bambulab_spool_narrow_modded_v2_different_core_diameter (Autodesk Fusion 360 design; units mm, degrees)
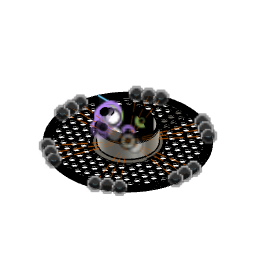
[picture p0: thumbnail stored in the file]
parameter "hole_distance_from_top" = 12.75
parameter "hole_distance_from_sides" = 32
parameter "lattice_thickness" = 3.75
parameter "lattice_diameter" = 10.25
parameter "hole_diameter" = 3.5 comment "The hole diameter around the rim"
parameter "center_core_outer_diameter" = 74 comment "The outer diameter the core should have, must be between 69 and 80 (inclusive)"
base_mesh_feature "Base Mesh Feature"
convert_mesh "Convert Mesh"
sketch "Sketch1" plane through (0, 0, -13.45) normal (0, 0, 1) x axis (-1, 0, 0)
  line L1 (91.1991, -17.1626) -> (97.9893, -17.84)
  line L2 (90.8249, -19.0441) -> (91.1991, -17.1626)
  line L3 (97.9893, -17.84) -> (90.8249, -19.0441)
  line L4 (94.8205, 15.0016) -> (94.8184, -14.9969)
  line L5 (34.4185, 89.6178) -> (60.3969, 74.6167)
  line L6 (-60.402, 74.6162) -> (-34.4215, 89.6136)
  line L7 (-94.8205, -15.0016) -> (-94.8184, 14.9969)
  line L8 (-34.4185, -89.6178) -> (-60.3969, -74.6167)
  line L9 (60.402, -74.6162) -> (34.4215, -89.6136)
  line L10 (0, 0) -> (47.4118, -82.1149)
  line L11 (-47.4077, -82.1173) -> (0, 0)
  line L12 (-94.8195, -0.0023) -> (0, 0)
  line L13 (-47.4118, 82.1149) -> (0, 0)
  line L14 (47.4077, 82.1173) -> (0, 0)
  line L15 (94.8195, 0.0023) -> (0, 0)
  line L16 (0, 0) -> (60.3969, 74.6167)
  line L17 (34.4185, 89.6178) -> (0, 0)
  line L18 (-34.4215, 89.6136) -> (0, 0)
  line L19 (-60.402, 74.6162) -> (0, 0)
  line L20 (-94.8184, 14.9969) -> (0, 0)
  line L21 (-94.8205, -15.0016) -> (0, 0)
  line L22 (-34.4185, -89.6178) -> (0, 0)
  line L23 (-60.3969, -74.6167) -> (0, 0)
  line L24 (34.4215, -89.6136) -> (0, 0)
  line L25 (60.402, -74.6162) -> (0, 0)
  line L26 (94.8184, -14.9969) -> (0, 0)
  line L27 (94.8205, 15.0016) -> (0, 0)
  circle C1 centre (94.8184, -14.9969) radius 2
  circle C2 centre (94.8205, 15.0016) radius 2
  circle C3 centre (60.3969, 74.6167) radius 2
  circle C4 centre (-34.4215, 89.6136) radius 2
  circle C5 centre (-94.8184, 14.9969) radius 2
  circle C6 centre (-60.3969, -74.6167) radius 2
  circle C7 centre (34.4215, -89.6136) radius 2
  circle C8 centre (34.4185, 89.6178) radius 2
  circle C9 centre (-60.402, 74.6162) radius 2
  circle C10 centre (-94.8205, -15.0016) radius 2
  circle C11 centre (-34.4185, -89.6178) radius 2
  circle C12 centre (60.402, -74.6162) radius 2
  point P1 (0, 0)
  point P7 (0, 0)
  point P5 (94.8184, -14.9969)
  point P18 (94.8184, -14.9969)
  point P6 (94.8205, 15.0016)
  point P19 (94.8205, 15.0016)
  point P8 (60.3969, 74.6167)
  point P20 (60.3969, 74.6167)
  point P13 (34.4185, 89.6178)
  point P21 (34.4185, 89.6178)
  point P9 (-34.4215, 89.6136)
  point P22 (-34.4215, 89.6136)
  point P14 (-60.402, 74.6162)
  point P23 (-60.402, 74.6162)
  point P10 (-94.8184, 14.9969)
  point P24 (-94.8184, 14.9969)
  point P15 (-94.8205, -15.0016)
  point P25 (-94.8205, -15.0016)
  point P11 (-60.3969, -74.6167)
  point P26 (-60.3969, -74.6167)
  point P16 (-34.4185, -89.6178)
  point P27 (-34.4185, -89.6178)
  point P12 (34.4215, -89.6136)
  point P28 (34.4215, -89.6136)
  point P17 (60.402, -74.6162)
  point P29 (60.402, -74.6162)
  point P30 (47.4118, -82.1149)
  point P31 (94.8195, 0.0023)
  point P32 (-47.4077, -82.1173)
  point P33 (-94.8195, -0.0023)
  point P34 (-47.4118, 82.1149)
  point P35 (47.4077, 82.1173)
  point P36 (47.4118, -82.1149)
  point P37 (0, 0)
  point P38 (-47.4077, -82.1173)
  point P39 (0, 0)
  point P40 (-94.8195, -0.0023)
  point P41 (0, 0)
  point P42 (-47.4118, 82.1149)
  point P43 (0, 0)
  point P44 (47.4077, 82.1173)
  point P45 (0, 0)
  point P46 (94.8195, 0.0023)
  point P47 (0, 0)
  point P48 (34.4185, 89.6178)
  point P49 (0, 0)
  point P50 (-34.4215, 89.6136)
  point P51 (0, 0)
  point P52 (-94.8184, 14.9969)
  point P53 (0, 0)
  point P54 (-94.8205, -15.0016)
  point P55 (-34.4185, -89.6178)
  point P56 (-60.3969, -74.6167)
  point P57 (0, 0)
  point P58 (60.402, -74.6162)
  point P59 (0, 0)
  point P60 (94.8184, -14.9969)
  point P61 (0, 0)
  point P62 (94.8205, 15.0016)
  coincident P1 P7
  coincident P5 P18
  coincident P6 P19
  coincident P8 P20
  coincident P13 P21
  coincident P9 P22
  coincident P14 P23
  coincident P10 P24
  coincident P15 P25
  coincident P11 P26
  coincident P16 P27
  coincident P12 P28
  coincident P17 P29
  midpoint L9 P30
  midpoint L4 P31
  midpoint L8 P32
  midpoint L7 P33
  midpoint L6 P34
  midpoint L5 P35
  coincident P30 P36
  coincident P1 P37
  coincident P32 P38
  coincident P1 P39
  coincident P33 P40
  coincident P7 P41
  coincident P34 P42
  coincident P7 P43
  coincident P35 P44
  coincident P1 P45
  coincident P31 P46
  coincident P7 P47
  coincident P13 P48
  coincident P7 P49
  coincident P9 P50
  coincident P7 P51
  coincident P10 P52
  coincident P7 P53
  coincident P15 P54
  coincident P16 P55
  coincident P11 P56
  coincident P1 P57
  coincident P17 P58
  coincident P1 P59
  coincident P5 P60
  coincident P7 P61
  coincident P6 P62
  dimension "d1" diameter C2 = 4
  dimension "d2" diameter C1 = 4
  dimension "d4" C-Pattern1-Angle = 360
  dimension "d6" C-Pattern2-Angle = 360
extrude "Extrude1" cut sketch "Sketch1" profile of C3 C4 C6 C7 C8 C9 C11 C12 against normal blind 11
sketch "Sketch2" plane through (0, 0, 0) normal (1, 0, 0) x axis (0, 1, 0)
  line L1 (0, -25) -> (0, 24)
  line L2 (-63, 0) -> (50, 0)
  circle C1 centre (-32, -12.75) radius 1.1
  circle C2 centre (32, -12.75) radius 1.1
  point P2 (-32, -12.75)
  point P3 (32, -12.75)
  vertical L1
  horizontal L2
  dimension "d9" diameter C2 = 2.2
  dimension "d10" diameter C1 = 2.2
  dimension "d11" distance P2 L1 = 32 (= "hole_distance_from_sides")
  dimension "d12" distance P3 L1 = 32 (= "hole_distance_from_sides")
  dimension "d13" distance P3 L2 = 12.75 (= "hole_distance_from_top")
  dimension "d16" distance P2 L2 = 12.75 (= "hole_distance_from_top")
work_plane "WorkPlane1" AlongDistance -61
work_plane "WorkPlane2" AlongDistance -64
work_plane "WorkPlane3" AlongDistance 64
work_plane "WorkPlane4" AlongDistance 65
sketch "Sketch3" plane through (64, 0, 0) normal (1, 0, 0) x axis (0, 1, 0)
  circle C1 centre (-32, -12.75) radius 1.1
  circle C2 centre (32, -12.75) radius 1.1
extrude "Extrude2" cut sketch "Sketch3" against normal blind 57
sketch "Sketch4" plane through (-61, 0, 0) normal (1, 0, 0) x axis (0, 1, 0)
  circle C1 centre (32, -12.75) radius 1.1
  circle C2 centre (-32, -12.75) radius 1.1
extrude "Extrude3" cut sketch "Sketch4" along normal blind 56
sketch "Sketch5" plane through (0, 65, 0) normal (0, 1, 0) x axis (1, 0, 0)
  line L1 (0, 26) -> (0, -23)
  line L2 (-49.4611, 0) -> (56, 0)
  circle C1 centre (32, 12.75) radius 1.1
  circle C2 centre (-32, 12.75) radius 1.1
  point P7 (-32, 12.75)
  point P6 (32, 12.75)
  vertical L1
  horizontal L2
  dimension "d25" diameter C1 = 2.2
  dimension "d26" diameter C2 = 2.2
  dimension "d27" distance L2 P7 = 12.75 (= "hole_distance_from_top")
  dimension "d28" distance L2 P6 = 12.75 (= "hole_distance_from_top")
  dimension "d29" distance L1 P6 = 32 (= "hole_distance_from_sides")
  dimension "d30" distance L1 P7 = 32 (= "hole_distance_from_sides")
extrude "Extrude4" cut sketch "Sketch5" profile of C1 C2 against normal blind 60
sketch "Sketch6" plane through (0, -64, 0) normal (0, 1, 0) x axis (1, 0, 0)
  circle C1 centre (32, 12.75) radius 1.1
  circle C2 centre (-32, 12.75) radius 1.1
extrude "Extrude5" cut sketch "Sketch6" along normal blind 60
sketch "Label" plane through (0, 0, -17.05) normal (0, 0, -1) x axis (1, 0, 0)
  line L1 (-1.2532, -46.0788) -> (-0.6281, -46.0197)
  line L2 (-1.8735, -46.1771) -> (-1.2532, -46.0788)
  line L3 (-2.4873, -46.3143) -> (-1.8735, -46.1771)
  line L4 (-3.0901, -46.4894) -> (-2.4873, -46.3143)
  line L5 (-3.6808, -46.7021) -> (-3.0901, -46.4894)
  line L6 (-0.6281, -46.0197) -> (0, -46.0001)
  line L7 (0.6281, -46.0197) -> (0, -46.0001)
  line L8 (1.2532, -46.0788) -> (0.6281, -46.0197)
  line L9 (1.8735, -46.1771) -> (1.2532, -46.0788)
  line L10 (2.4872, -46.3143) -> (1.8735, -46.1771)
  line L11 (3.0901, -46.4894) -> (2.4872, -46.3143)
  line L12 (3.6808, -46.7021) -> (3.0901, -46.4894)
  line L13 (4.2582, -46.9519) -> (3.6808, -46.7021)
  line L14 (4.8175, -47.2369) -> (4.2582, -46.9519)
  line L15 (5.3579, -47.5565) -> (4.8175, -47.2369)
  line L16 (5.878, -47.91) -> (5.3579, -47.5565)
  line L17 (6.3742, -48.2949) -> (5.878, -47.91)
  line L18 (6.8453, -48.7102) -> (6.3742, -48.2949)
  line L19 (7.2897, -49.1546) -> (6.8453, -48.7102)
  line L20 (7.7051, -49.6258) -> (7.2897, -49.1546)
  line L21 (8.0901, -50.1221) -> (7.7051, -49.6258)
  line L22 (8.4431, -50.6416) -> (8.0901, -50.1221)
  line L23 (8.7631, -51.1825) -> (8.4431, -50.6416)
  line L24 (9.0483, -51.7422) -> (8.7631, -51.1825)
  line L25 (9.2976, -52.3185) -> (9.0483, -51.7422)
  line L26 (9.5106, -52.91) -> (9.2976, -52.3185)
  line L27 (9.6858, -53.5131) -> (9.5106, -52.91)
  line L28 (9.8228, -54.1259) -> (9.6858, -53.5131)
  line L29 (9.9212, -54.7468) -> (9.8228, -54.1259)
  line L30 (9.9802, -55.3716) -> (9.9212, -54.7468)
  line L31 (10, -56) -> (9.9802, -55.3716)
  line L32 (10, -82) -> (10, -56)
  line L33 (-9.2976, -52.3185) -> (-9.0483, -51.7422)
  line L34 (-9.0483, -51.7422) -> (-8.7631, -51.1825)
  line L35 (-8.7631, -51.1825) -> (-8.4431, -50.6416)
  line L36 (-8.4431, -50.6416) -> (-8.0901, -50.1221)
  line L37 (-8.0901, -50.1221) -> (-7.7051, -49.6258)
  line L38 (-7.7051, -49.6258) -> (-7.2897, -49.1546)
  line L39 (-7.2897, -49.1546) -> (-6.8453, -48.7102)
  line L40 (-6.8453, -48.7102) -> (-6.3742, -48.2949)
  line L41 (-6.3742, -48.2949) -> (-5.878, -47.91)
  line L42 (-5.878, -47.91) -> (-5.3579, -47.5565)
  line L43 (-5.3579, -47.5565) -> (-4.8175, -47.2369)
  line L44 (-4.8175, -47.2369) -> (-4.2582, -46.9519)
  line L45 (-4.2582, -46.9519) -> (-3.6808, -46.7021)
  line L46 (-9.5106, -52.91) -> (-9.2976, -52.3185)
  line L47 (-9.6858, -53.5131) -> (-9.5106, -52.91)
  line L48 (-9.8228, -54.1259) -> (-9.6858, -53.5131)
  line L49 (-9.9212, -54.7468) -> (-9.8228, -54.1259)
  line L50 (-9.9802, -55.3716) -> (-9.9212, -54.7468)
  line L51 (-10, -56) -> (-9.9802, -55.3716)
  line L52 (-10, -82) -> (-10, -56)
  line L53 (9.9802, -82.6284) -> (10, -82)
  line L54 (9.9212, -83.2532) -> (9.9802, -82.6284)
  line L55 (9.8228, -83.8741) -> (9.9212, -83.2532)
  line L56 (9.6858, -84.4869) -> (9.8228, -83.8741)
  line L57 (9.5106, -85.09) -> (9.6858, -84.4869)
  line L58 (9.2976, -85.6815) -> (9.5106, -85.09)
  line L59 (9.0483, -86.2578) -> (9.2976, -85.6815)
  line L60 (8.7631, -86.8175) -> (9.0483, -86.2578)
  line L61 (8.4431, -87.3584) -> (8.7631, -86.8175)
  line L62 (8.0901, -87.8779) -> (8.4431, -87.3584)
  line L63 (7.7051, -88.3742) -> (8.0901, -87.8779)
  line L64 (7.2897, -88.8454) -> (7.7051, -88.3742)
  line L65 (6.8453, -89.2898) -> (7.2897, -88.8454)
  line L66 (6.3742, -89.7051) -> (6.8453, -89.2898)
  line L67 (5.878, -90.09) -> (6.3742, -89.7051)
  line L68 (5.3579, -90.4435) -> (5.878, -90.09)
  line L69 (4.8175, -90.7631) -> (5.3579, -90.4435)
  line L70 (4.2582, -91.0481) -> (4.8175, -90.7631)
  line L71 (3.6808, -91.2979) -> (4.2582, -91.0481)
  line L72 (3.0901, -91.5106) -> (3.6808, -91.2979)
  line L73 (2.4872, -91.6857) -> (3.0901, -91.5106)
  line L74 (1.8735, -91.8229) -> (2.4872, -91.6857)
  line L75 (1.2532, -91.9212) -> (1.8735, -91.8229)
  line L76 (0.6281, -91.9803) -> (1.2532, -91.9212)
  line L77 (0, -92) -> (0.6281, -91.9803)
  line L78 (0, -92) -> (-0.6281, -91.9803)
  line L79 (-0.6281, -91.9803) -> (-1.2532, -91.9212)
  line L80 (-1.2532, -91.9212) -> (-1.8735, -91.8229)
  line L81 (-1.8735, -91.8229) -> (-2.4873, -91.6857)
  line L82 (-2.4873, -91.6857) -> (-3.0901, -91.5106)
  line L83 (-3.0901, -91.5106) -> (-3.6808, -91.2979)
  line L84 (-3.6808, -91.2979) -> (-4.2582, -91.0481)
  line L85 (-4.2582, -91.0481) -> (-4.8175, -90.7631)
  line L86 (-4.8175, -90.7631) -> (-5.3579, -90.4435)
  line L87 (-5.3579, -90.4435) -> (-5.878, -90.09)
  line L88 (-5.878, -90.09) -> (-6.3742, -89.7051)
  line L89 (-6.3742, -89.7051) -> (-6.8453, -89.2898)
  line L90 (-6.8453, -89.2898) -> (-7.2897, -88.8454)
  line L91 (-7.2897, -88.8454) -> (-7.7051, -88.3742)
  line L92 (-7.7051, -88.3742) -> (-8.0901, -87.8779)
  line L93 (-8.0901, -87.8779) -> (-8.4431, -87.3584)
  line L94 (-8.4431, -87.3584) -> (-8.7631, -86.8175)
  line L95 (-8.7631, -86.8175) -> (-9.0483, -86.2578)
  line L96 (-9.0483, -86.2578) -> (-9.2976, -85.6815)
  line L97 (-9.2976, -85.6815) -> (-9.5106, -85.09)
  line L98 (-9.5106, -85.09) -> (-9.6858, -84.4869)
  line L99 (-9.6858, -84.4869) -> (-9.8228, -83.8741)
  line L100 (-9.8228, -83.8741) -> (-9.9212, -83.2532)
  line L101 (-9.9212, -83.2532) -> (-9.9802, -82.6284)
  line L102 (-9.9802, -82.6284) -> (-10, -82)
  line L103 (-10.3182, -83.3033) -> (-10.3796, -82.6536)
  line L104 (-10.2159, -83.9491) -> (-10.3182, -83.3033)
  line L105 (-10.0734, -84.5864) -> (-10.2159, -83.9491)
  line L106 (-9.8912, -85.2136) -> (-10.0734, -84.5864)
  line L107 (-9.6697, -85.8289) -> (-9.8912, -85.2136)
  line L108 (-9.4104, -86.4282) -> (-9.6697, -85.8289)
  line L109 (-9.1138, -87.0103) -> (-9.4104, -86.4282)
  line L110 (-8.781, -87.5728) -> (-9.1138, -87.0103)
  line L111 (-8.4139, -88.1131) -> (-8.781, -87.5728)
  line L112 (-8.0135, -88.6293) -> (-8.4139, -88.1131)
  line L113 (-7.5814, -89.1194) -> (-8.0135, -88.6293)
  line L114 (-7.1193, -89.5816) -> (-7.5814, -89.1194)
  line L115 (-6.6293, -90.0135) -> (-7.1193, -89.5816)
  line L116 (-6.1133, -90.4137) -> (-6.6293, -90.0135)
  line L117 (-5.5723, -90.7814) -> (-6.1133, -90.4137)
  line L118 (-5.0103, -91.1138) -> (-5.5723, -90.7814)
  line L119 (-4.4285, -91.4102) -> (-5.0103, -91.1138)
  line L120 (-3.8281, -91.67) -> (-4.4285, -91.4102)
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  dimension "d59" = 0.4
sketch "Sketch7" plane through (0, 0, -14.55) normal (0, 0, 1) x axis (-1, 0, 0)
  line L1 (-2.5625, -4.4384) -> (-5.125, 0)
  line L2 (-5.125, 0) -> (-2.5625, 4.4384)
  line L3 (8.3726, -10.7518) -> (5.8101, -6.3134)
  line L4 (16.0601, -6.3134) -> (13.4976, -10.7518)
  line L5 (13.4976, -10.7518) -> (8.3726, -10.7518)
  line L6 (2.5625, -8.1884) -> (5.125, -12.6268)
  line L7 (5.125, -12.6268) -> (2.5625, -17.0651)
  line L8 (16.0601, -17.0651) -> (16.0601, 10.7518)
  line L9 (2.5625, -17.0651) -> (-2.5625, -17.0651)
  line L10 (5.125, 0) -> (2.5625, -4.4384)
  line L11 (-2.5625, 4.4384) -> (2.5625, 4.4384)
  line L12 (-5.125, -17.0651) -> (16.0601, -17.0651)
  line L13 (-5.125, 10.7518) -> (16.0601, 10.7518)
  line L14 (-37, 0) -> (37, 0)
  line L15 (2.5625, -4.4384) -> (-2.5625, -4.4384)
  line L16 (-2.5625, -17.0651) -> (-5.125, -12.6268)
  line L17 (2.5625, 4.4384) -> (5.125, 0)
  line L18 (13.4976, 10.7518) -> (16.0601, 6.3134)
  line L19 (5.8101, 6.3134) -> (8.3726, 10.7518)
  line L20 (16.0601, 6.3134) -> (13.4976, 1.875)
  line L21 (13.4976, 1.875) -> (8.3726, 1.875)
  line L22 (-2.5625, -8.1884) -> (2.5625, -8.1884)
  line L23 (8.3726, 10.7518) -> (13.4976, 10.7518)
  line L24 (8.3726, -1.875) -> (13.4976, -1.875)
  line L25 (8.3726, 1.875) -> (5.8101, 6.3134)
  line L26 (5.8101, -6.3134) -> (8.3726, -1.875)
  line L27 (13.4976, -1.875) -> (16.0601, -6.3134)
  line L28 (-5.125, -17.0651) -> (-5.125, 10.7518)
  line L29 (0, -45.5) -> (0, 45.5)
  line L30 (-5.125, -12.6268) -> (-2.5625, -8.1884)
  line L31 (-100.8005, -108.8944) -> (-103.363, -113.3327)
  line L32 (-103.363, -113.3327) -> (-108.488, -113.3327)
  line L33 (-108.488, -113.3327) -> (-111.0505, -108.8944)
  line L34 (-111.0505, -108.8944) -> (-108.488, -104.456)
  line L35 (-108.488, -104.456) -> (-103.363, -104.456)
  line L36 (-103.363, -104.456) -> (-100.8005, -108.8944)
  line L37 (-97.5529, -107.0194) -> (-100.1154, -102.581)
  line L38 (-92.4279, -107.0194) -> (-97.5529, -107.0194)
  line L39 (-89.8654, -102.581) -> (-92.4279, -107.0194)
  line L40 (-92.4279, -98.1426) -> (-89.8654, -102.581)
  line L41 (-97.5529, -98.1426) -> (-92.4279, -98.1426)
  line L42 (-100.1154, -102.581) -> (-97.5529, -98.1426)
  line L43 (-100.8005, -96.2676) -> (-103.363, -100.706)
  line L44 (-103.363, -100.706) -> (-108.488, -100.706)
  line L45 (-108.488, -100.706) -> (-111.0505, -96.2676)
  line L46 (-111.0505, -96.2676) -> (-108.488, -91.8292)
  line L47 (-108.488, -91.8292) -> (-103.363, -91.8292)
  line L48 (-103.363, -91.8292) -> (-100.8005, -96.2676)
  line L49 (-97.5529, -94.3926) -> (-100.1154, -89.9542)
  line L50 (-92.4279, -94.3926) -> (-97.5529, -94.3926)
  line L51 (-89.8654, -89.9542) -> (-92.4279, -94.3926)
  line L52 (-92.4279, -85.5158) -> (-89.8654, -89.9542)
  line L53 (-100.1154, -89.9542) -> (-97.5529, -85.5158)
  line L54 (-97.5529, -85.5158) -> (-92.4279, -85.5158)
  line L55 (-79.6154, -108.8944) -> (-82.1779, -113.3327)
  line L56 (-82.1779, -113.3327) -> (-87.3029, -113.3327)
  line L57 (-87.3029, -113.3327) -> (-89.8654, -108.8944)
  line L58 (-89.8654, -108.8944) -> (-87.3029, -104.456)
  line L59 (-87.3029, -104.456) -> (-82.1779, -104.456)
  line L60 (-82.1779, -104.456) -> (-79.6154, -108.8944)
  line L61 (-76.3678, -107.0194) -> (-78.9303, -102.581)
  line L62 (-71.2428, -107.0194) -> (-76.3678, -107.0194)
  line L63 (-68.6803, -102.581) -> (-71.2428, -107.0194)
  line L64 (-71.2428, -98.1426) -> (-68.6803, -102.581)
  line L65 (-76.3678, -98.1426) -> (-71.2428, -98.1426)
  line L66 (-78.9303, -102.581) -> (-76.3678, -98.1426)
  line L67 (-79.6154, -96.2676) -> (-82.1779, -100.706)
  line L68 (-82.1779, -100.706) -> (-87.3029, -100.706)
  line L69 (-87.3029, -100.706) -> (-89.8654, -96.2676)
  line L70 (-89.8654, -96.2676) -> (-87.3029, -91.8292)
  line L71 (-87.3029, -91.8292) -> (-82.1779, -91.8292)
  line L72 (-82.1779, -91.8292) -> (-79.6154, -96.2676)
  line L73 (-76.3678, -94.3926) -> (-78.9303, -89.9542)
  line L74 (-71.2428, -94.3926) -> (-76.3678, -94.3926)
  line L75 (-68.6803, -89.9542) -> (-71.2428, -94.3926)
  line L76 (-71.2428, -85.5158) -> (-68.6803, -89.9542)
  line L77 (-78.9303, -89.9542) -> (-76.3678, -85.5158)
  line L78 (-76.3678, -85.5158) -> (-71.2428, -85.5158)
  line L79 (-58.4303, -108.8944) -> (-60.9928, -113.3327)
  line L80 (-60.9928, -113.3327) -> (-66.1178, -113.3327)
  line L81 (-66.1178, -113.3327) -> (-68.6803, -108.8944)
  line L82 (-68.6803, -108.8944) -> (-66.1178, -104.456)
  line L83 (-66.1178, -104.456) -> (-60.9928, -104.456)
  line L84 (-60.9928, -104.456) -> (-58.4303, -108.8944)
  line L85 (-55.1827, -107.0194) -> (-57.7452, -102.581)
  line L86 (-50.0577, -107.0194) -> (-55.1827, -107.0194)
  line L87 (-47.4952, -102.581) -> (-50.0577, -107.0194)
  line L88 (-50.0577, -98.1426) -> (-47.4952, -102.581)
  line L89 (-55.1827, -98.1426) -> (-50.0577, -98.1426)
  line L90 (-57.7452, -102.581) -> (-55.1827, -98.1426)
  line L91 (-58.4303, -96.2676) -> (-60.9928, -100.706)
  line L92 (-60.9928, -100.706) -> (-66.1178, -100.706)
  line L93 (-66.1178, -100.706) -> (-68.6803, -96.2676)
  line L94 (-68.6803, -96.2676) -> (-66.1178, -91.8292)
  line L95 (-66.1178, -91.8292) -> (-60.9928, -91.8292)
  line L96 (-60.9928, -91.8292) -> (-58.4303, -96.2676)
  line L97 (-55.1827, -94.3926) -> (-57.7452, -89.9542)
  line L98 (-50.0577, -94.3926) -> (-55.1827, -94.3926)
  line L99 (-47.4952, -89.9542) -> (-50.0577, -94.3926)
  line L100 (-50.0577, -85.5158) -> (-47.4952, -89.9542)
  line L101 (-57.7452, -89.9542) -> (-55.1827, -85.5158)
  line L102 (-55.1827, -85.5158) -> (-50.0577, -85.5158)
  line L103 (-37.2452, -108.8944) -> (-39.8077, -113.3327)
  line L104 (-39.8077, -113.3327) -> (-44.9327, -113.3327)
  line L105 (-44.9327, -113.3327) -> (-47.4952, -108.8944)
  line L106 (-47.4952, -108.8944) -> (-44.9327, -104.456)
  line L107 (-44.9327, -104.456) -> (-39.8077, -104.456)
  line L108 (-39.8077, -104.456) -> (-37.2452, -108.8944)
  line L109 (-33.9976, -107.0194) -> (-36.5601, -102.581)
  line L110 (-28.8726, -107.0194) -> (-33.9976, -107.0194)
  line L111 (-26.3101, -102.581) -> (-28.8726, -107.0194)
  line L112 (-28.8726, -98.1426) -> (-26.3101, -102.581)
  line L113 (-33.9976, -98.1426) -> (-28.8726, -98.1426)
  line L114 (-36.5601, -102.581) -> (-33.9976, -98.1426)
  line L115 (-37.2452, -96.2676) -> (-39.8077, -100.706)
  line L116 (-39.8077, -100.706) -> (-44.9327, -100.706)
  line L117 (-44.9327, -100.706) -> (-47.4952, -96.2676)
  line L118 (-47.4952, -96.2676) -> (-44.9327, -91.8292)
  line L119 (-44.9327, -91.8292) -> (-39.8077, -91.8292)
  line L120 (-39.8077, -91.8292) -> (-37.2452, -96.2676)
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  point P1 (0, 0)
  point P2 (0, 0)
  point P3 (0, 0)
  point P4 (0, 0)
  point P5 (0, 0)
  point P41 (0, 0)
  point P6 (0, 0)
  point P7 (0, 0)
  point P14 (0, 0)
  point P21 (0, -12.6268)
  point P10 (-5.125, 0)
  point P27 (16.0601, -6.3134)
  point P43 (16.0601, -17.0651)
  point P44 (-5.125, -17.0651)
  point P40 (-5.125, 10.7518)
  point P42 (16.0601, 10.7518)
  point P2661 (0, 0)
  point P13 (5.125, 0)
  point P8 (2.5625, 4.4384)
  point P11 (-2.5625, -4.4384)
  point P16 (5.125, -12.6268)
  point P19 (-5.125, -12.6268)
  point P15 (2.5625, -17.0651)
  point P18 (-2.5625, -8.1884)
  point P30 (5.8101, -6.3134)
  point P33 (16.0601, 6.3134)
  point P36 (5.8101, 6.3134)
  coincident P1 P2
  coincident P2 P3
  coincident P1 P4
  coincident P5 P41
  coincident P6 P41
  coincident P7 P41
  coincident P6 P14
  vertical L29
  horizontal L14
  coincident P41 L29
  midpoint P5 L14
  midpoint P41 L29
  coincident P21 L29
  parallel L14 L15
  parallel L5 L14
  parallel L14 L21
  vertical L28
  vertical L8
  coincident P10 L28
  coincident P27 L8
  perpendicular L8 L13
  horizontal L12
  collinear L13 L23
  collinear L9 L12
  coincident P43 L8
  coincident P44 L28
  coincident P40 L13
  coincident P42 L8
  coincident P2 P2661
  dimension "d35" diameter = 183.4
  dimension "d38" diameter = 179.65 (= "183.4 mm - lattice_thickness")
  dimension "d63" distance P10 P13 = 10.25 (= "lattice_diameter")
  dimension "d64" distance P8 P11 = 10.25 (= "lattice_diameter")
  dimension "d65" distance P16 P19 = 10.25 (= "lattice_diameter")
  dimension "d66" distance P15 P18 = 10.25 (= "lattice_diameter")
  dimension "d67" distance L15 L22 = 3.75 (= "lattice_thickness")
  dimension "d68" distance P27 P30 = 10.25 (= "lattice_diameter")
  dimension "d69" distance L10 L26 = 3.75 (= "lattice_thickness")
  dimension "d70" distance L3 L6 = 3.75 (= "lattice_thickness")
  dimension "d71" distance P33 P36 = 10.25 (= "lattice_diameter")
  dimension "d72" distance L21 L24 = 3.75 (= "lattice_thickness")
  dimension "d73" distance L17 L25 = 3.75 (= "lattice_thickness")
  dimension "d74" distance P43 P44 = 21.1851
  dimension "d75" distance P42 P43 = 27.8169
  dimension "d56" diameter = 89
  dimension "d54" R-Pattern1-uDistance = 21.1851
  dimension "d55" R-Pattern1-vDistance = 24.0669 (= "27.816899 mm - lattice_thickness")
extrude "Extrude6" cut sketch "Sketch7" distance 30
extrude "Extrude7" add sketch "Label" profile of L1 L2 L3 L4 L5 L6 L7 L8 L9 L10 L11 L12 L13 L14 L15 L16 L17 L18 L19 L20 L21 L22 L23 L24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 against normal blind 0.4
sketch "Sketch13" plane through (-3.8901, 27.2222, 0) normal (0.1415, -0.9899, 0) x axis (0.9899, 0.1415, 0)
  line L1 (3.3587, 0) -> (-3.6413, 0)
  line L2 (-0.1413, 3.5) -> (-3.6413, 0)
  line L3 (3.3587, 0) -> (-0.1413, 3.5)
  line L4 (-0.1413, 0) -> (-0.1413, 3.5)
  point P2 (-0.1413, 0)
  point P6 (-0.1413, 0)
  point P5 (-0.1413, 3.5)
  horizontal L1
  coincident P2 P6
  coincident P2 L1
  equal L2 L3
  perpendicular L1 L4
  dimension "d92" distance P5 P6 = 3.5
  dimension "d93" angle L2 L3 = 90
sketch "Sketch15" plane through (3.8901, -27.2222, 0) normal (-0.1415, 0.9899, 0) x axis (-0.9899, -0.1415, 0)
  line L1 (-0.1438, 3.5) -> (3.3562, 0)
  line L2 (-3.6438, 0) -> (-0.1438, 3.5)
  line L3 (-3.6438, 0) -> (3.3562, 0)
extrude "Extrude10" cut sketch "Sketch13" profile of L1 L2 L3 along normal blind 5 and against normal blind 0.5
chamfer "Chamfer1" distance 0.5 Rotate Angle 45
extrude "Extrude11" cut sketch "Sketch15" along normal blind 5 and against normal blind 0.5
chamfer "Chamfer2" distance 0.5 Rotate Angle 45
extrude "Extrude12" add sketch "Sketch1" profile of C1 C2 C3 C4 C5 C6 C7 C8 C9 C10 C11 C12 against normal blind 3.6
work_plane "WorkPlane5" RotateAngle 45
sketch "Sketch16" plane through (17.2108, -44.8068, -13.45) normal (-0.6601, -0.2535, 0.7071) x axis (0.3586, -0.9335, 0)
  circle C1 centre (48, 0) radius 1.75
  dimension "d110" diameter C1 = 3.5 (= "hole_diameter")
extrude "Extrude13" new body sketch "Sketch16" distance 20
work_plane "WorkPlane6" RotateAngle -45
sketch "Sketch17" plane through (30.201, -37.3081, -13.45) normal (0.5496, 0.4449, 0.7071) x axis (0.6292, -0.7773, 0)
  circle C1 centre (48, 0) radius 1.75
  dimension "d114" diameter C1 = 3.5 (= "hole_diameter")
extrude "Extrude14" new body sketch "Sketch17" distance 20
circular_pattern "C-Pattern1" TotalAngle 360
combine "Combine1"
sketch "Outer Wall Change" plane through (0, 0, 0) normal (0, 1, 0) x axis (1, 0, 0)
  line L1 (-44.5, 14.55) -> (-44.5, 17.05)
  line L2 (-41.1456, 14.55) -> (-44.5, 14.55)
  line L3 (-40.65, 14.05) -> (-41.1456, 14.55)
  line L4 (-40.65, -7.65) -> (-40.65, 14.05)
  line L5 (-39.65, -8.65) -> (-40.65, -7.65)
  line L6 (-37.7, -3.65) -> (-37.6972, -10.85)
  line L7 (-37.6952, -3.65) -> (-37.7, -3.65)
  line L8 (-38.3993, -10.85) -> (-37.6972, -10.85)
  line L9 (-38.895, -10.05) -> (-38.3993, -10.85)
  line L10 (-39.65, -8.65) -> (-38.8955, -8.65)
  line L11 (-29.7, -10.8469) -> (-37.6972, -10.85)
  line L12 (-29.7, -3.65) -> (-29.7, -14.1994)
  line L13 (-37, 14.05) -> (-37, -7.65)
  line L14 (11.565, 14.05) -> (-40.65, 14.05)
  line L15 (-22, 14.55) -> (-41.1456, 14.55)
  line L16 (-37.4956, 14.55) -> (-37, 14.05)
  line L17 (-26.4182, -7.65) -> (-40.65, -7.65)
  line L18 (-25, -8.65) -> (-39.65, -8.65)
  line L19 (-36, -8.65) -> (-37, -7.65)
  line L20 (-35.2456, -8.65) -> (-36, -8.65)
  line L21 (-38.8955, -8.65) -> (-38.895, -10.05)
  line L22 (-26.3686, -10.0451) -> (-38.895, -10.05)
  line L23 (-35.245, -10.0486) -> (-35.2456, -8.65)
  line L24 (-34.7493, -10.8488) -> (-35.245, -10.0486)
  line L25 (-34.0472, -10.8486) -> (-34.7493, -10.8488)
  line L26 (-34.0472, -3.6429) -> (-34.0472, -10.8486)
  line L27 (-37.6952, -3.65) -> (-29.6939, -3.65)
  line L28 (-34.0472, 14.55) -> (-34.0472, -3.6429)
  line L29 (-37.4956, 14.55) -> (-34.0472, 14.55)
  line L30 (-34.0472, -27.4165) -> (-34.0472, -10.8486)
  line L31 (-49.0472, -27.4165) -> (-34.0472, -27.4165)
  line L32 (-49.0472, 14.55) -> (-49.0472, -27.4165)
  line L33 (-49.0472, 14.55) -> (-44.5, 14.55)
  line L34 (-37.4956, 14.55) -> (-41.1456, 14.55)
  line L35 (-39.65, -8.65) -> (-36, -8.65)
  line L36 (-40.65, -7.65) -> (-37, -7.65)
  line L37 (-38.895, -10.05) -> (-35.245, -10.0486)
  line L38 (-38.3993, -10.85) -> (-34.7493, -10.8488)
  line L39 (-37.6972, -10.85) -> (-34.0472, -10.8486)
  point P8 (-37.6972, -10.85)
  point P11 (-37.6972, -10.85)
  point P7 (-39.65, -8.65)
  point P15 (-39.65, -8.65)
  point P18 (-29.7, -14.1994)
  point P19 (-29.7, -14.1994)
  point P16 (-29.7, -10.8469)
  point P5 (-40.65, 14.05)
  point P23 (-40.65, 14.05)
  point P22 (-37, 14.05)
  point P4 (-41.1456, 14.55)
  point P25 (-41.1456, 14.55)
  point P27 (-37.4956, 14.55)
  point P6 (-40.65, -7.65)
  point P28 (-40.65, -7.65)
  point P30 (-39.65, -8.65)
  point P32 (-36, -8.65)
  point P33 (-35.2456, -8.65)
  point P35 (-35.245, -10.0486)
  point P36 (-34.7493, -10.8488)
  point P37 (-34.0472, -10.8486)
  point P41 (-34.0472, 14.55)
  point P44 (-49.0472, 14.55)
  point P3 (-44.5, 14.55)
  point P45 (-44.5, 14.55)
  point P46 (-39.65, -8.65)
  point P42 (-34.0472, -27.4165)
  point P43 (-49.0472, -27.4165)
  point P1 (0, 0)
  coincident P8 P11
  coincident P7 P15
  horizontal L10
  perpendicular L6 L11
  coincident P18 P19
  vertical L12
  coincident P16 L12
  coincident P5 P23
  horizontal L14
  coincident P22 L14
  vertical L13
  equal L4 L13
  coincident P4 P25
  parallel L2 L15
  coincident L15 P27
  equal L3 L16
  coincident P6 P28
  perpendicular L4 L17
  coincident P7 P30
  parallel L10 L18
  coincident L18 P32
  coincident L18 P33
  parallel L18 L20
  perpendicular L6 L22
  coincident L22 P35
  perpendicular L22 L23
  coincident L11 P36
  coincident L11 P37
  coincident L15 P41
  perpendicular L15 L28
  collinear L26 L30
  perpendicular L30 L31
  perpendicular L31 L32
  coincident L2 P44
  coincident P3 P45
  coincident P7 P46
  equal L35 L36
  equal L36 L37
  equal L36 L38
  equal L36 L39
  dimension "d121" angle L26 L27 = 90
  dimension "d122" distance P42 P43 = 15
  dimension "d126" distance P1 P22 = 37 (= "center_core_outer_diameter / 2")
revolve "Revolve1" sketch "Outer Wall Change" AlongAngle 360 bodies "Center Core Cut Outer Wall"
revolve "Revolve2" sketch "Outer Wall Change" AlongAngle 360 bodies "Center Core New Outer Wall"
combine "Combine2" bodies "Center Core Cut Outer Wall"
combine "Combine3" bodies "Center Core New Outer Wall"
named bodies: "bambulab_spool_narrow", "Center Core Cut Outer Wall", "Center Core New Outer Wall"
